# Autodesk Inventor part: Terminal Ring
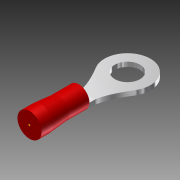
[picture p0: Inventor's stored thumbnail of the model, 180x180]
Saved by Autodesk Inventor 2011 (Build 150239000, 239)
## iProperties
Created: 2005-03
Part Number: Terminal Ring
Document SubType Name: Modeling
Designer: Autodesk Inc.
Density: 1 g/cm^3
Categories: <MemberInstance><Categories><Category DisplayName="" Mnemonic="CABLEANDHARNESS" InternalName="e4a7e005-5e42-4d16-b293-125e7f0d0512"><Category DisplayName="" Mne
Mass: 0.139065 g
Surface Area: 2.60388 cm^2
Volume: 0.139065 cm^3
GlobalPropertyList: <PropertyList/>
Company: Autodesk Inc.
Author: Autodesk Inc.
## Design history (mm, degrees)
sketch "Sketch1"
  geometry: L1 (-1.32, -6.88)-(1.32, -6.88); L2 (0, 0)-(0, -6.88); C1 r 2.17 at (0, 0); A1 r 3.96 centre (0, 0) between (3.378, -2.067) and (-3.378, -2.067); 4 further points
  constraints: 4 end point, 3 vertical alignment, 2 centre point, 2 coincident, 2 point on circle, 1 horizontal, 1 horizontal alignment, 1 midpoint, 1 perpendicular, 1 symmetric about line, 1 vertical, 7 other
  dimensions: "d0" = 7.92 diameter of A1; "d2" = 2.64 distance of L1.start L1.end; "d3" = 1.79 radial gap between concentric circles of A1 C1; "d4" = 6.88 distance from line of A1.centre L1
extrude "Extrusion1" new body sketch "Sketch1" distance "d5" = 0.79; taper "d6" = 0 deg
workplane "Work Plane3"
sketch "Sketch4"
  geometry: C1 r 1.82 at (0, 0)
  constraints: 1 centre point
extrude "Extrusion3" join sketch "Sketch4" distance "d19" = 3.5; taper "d20" = 0 deg
workplane "Work Plane5"
sketch "Sketch5"
  geometry: C1 r 1.82 at (0, 0) reference; C2 r 1.82 at (0, 0)
  constraints: 1 centre point
extrude "Extrusion4" join sketch "Sketch5" distance "d22" = 3; taper "d23" = 5 deg
workplane "Work Plane6"
sketch "Sketch6"
  geometry: C1 r 2.082 at (0, 0) reference; C2 r 2.082 at (0, 0)
  constraints: 2 centre point, 1 concentric, 1 other
extrude "Extrusion5" join sketch "Sketch6" distance "d25" = 2; taper "d26" = 0 deg
workplane "Work Plane4"
sketch "Sketch8"
  geometry: L1 (2.64, 0.79)-(0, 0.79) reference; L2 (0, 0)-(0, 0.79) reference; L3 (0, 0)-(2.64, 0) reference; L4 (2.64, 0)-(2.64, 0.79) reference
extrude "Extrusion6" join sketch "Sketch8" stored distance "d30" = 10; taper "d31" = -2 deg
sketch "Sketch9"
  geometry: C1 r 2.082 at (0, 0) reference; 1 further point
  constraints: 1 coincident
node "1"
body "Solid1"
